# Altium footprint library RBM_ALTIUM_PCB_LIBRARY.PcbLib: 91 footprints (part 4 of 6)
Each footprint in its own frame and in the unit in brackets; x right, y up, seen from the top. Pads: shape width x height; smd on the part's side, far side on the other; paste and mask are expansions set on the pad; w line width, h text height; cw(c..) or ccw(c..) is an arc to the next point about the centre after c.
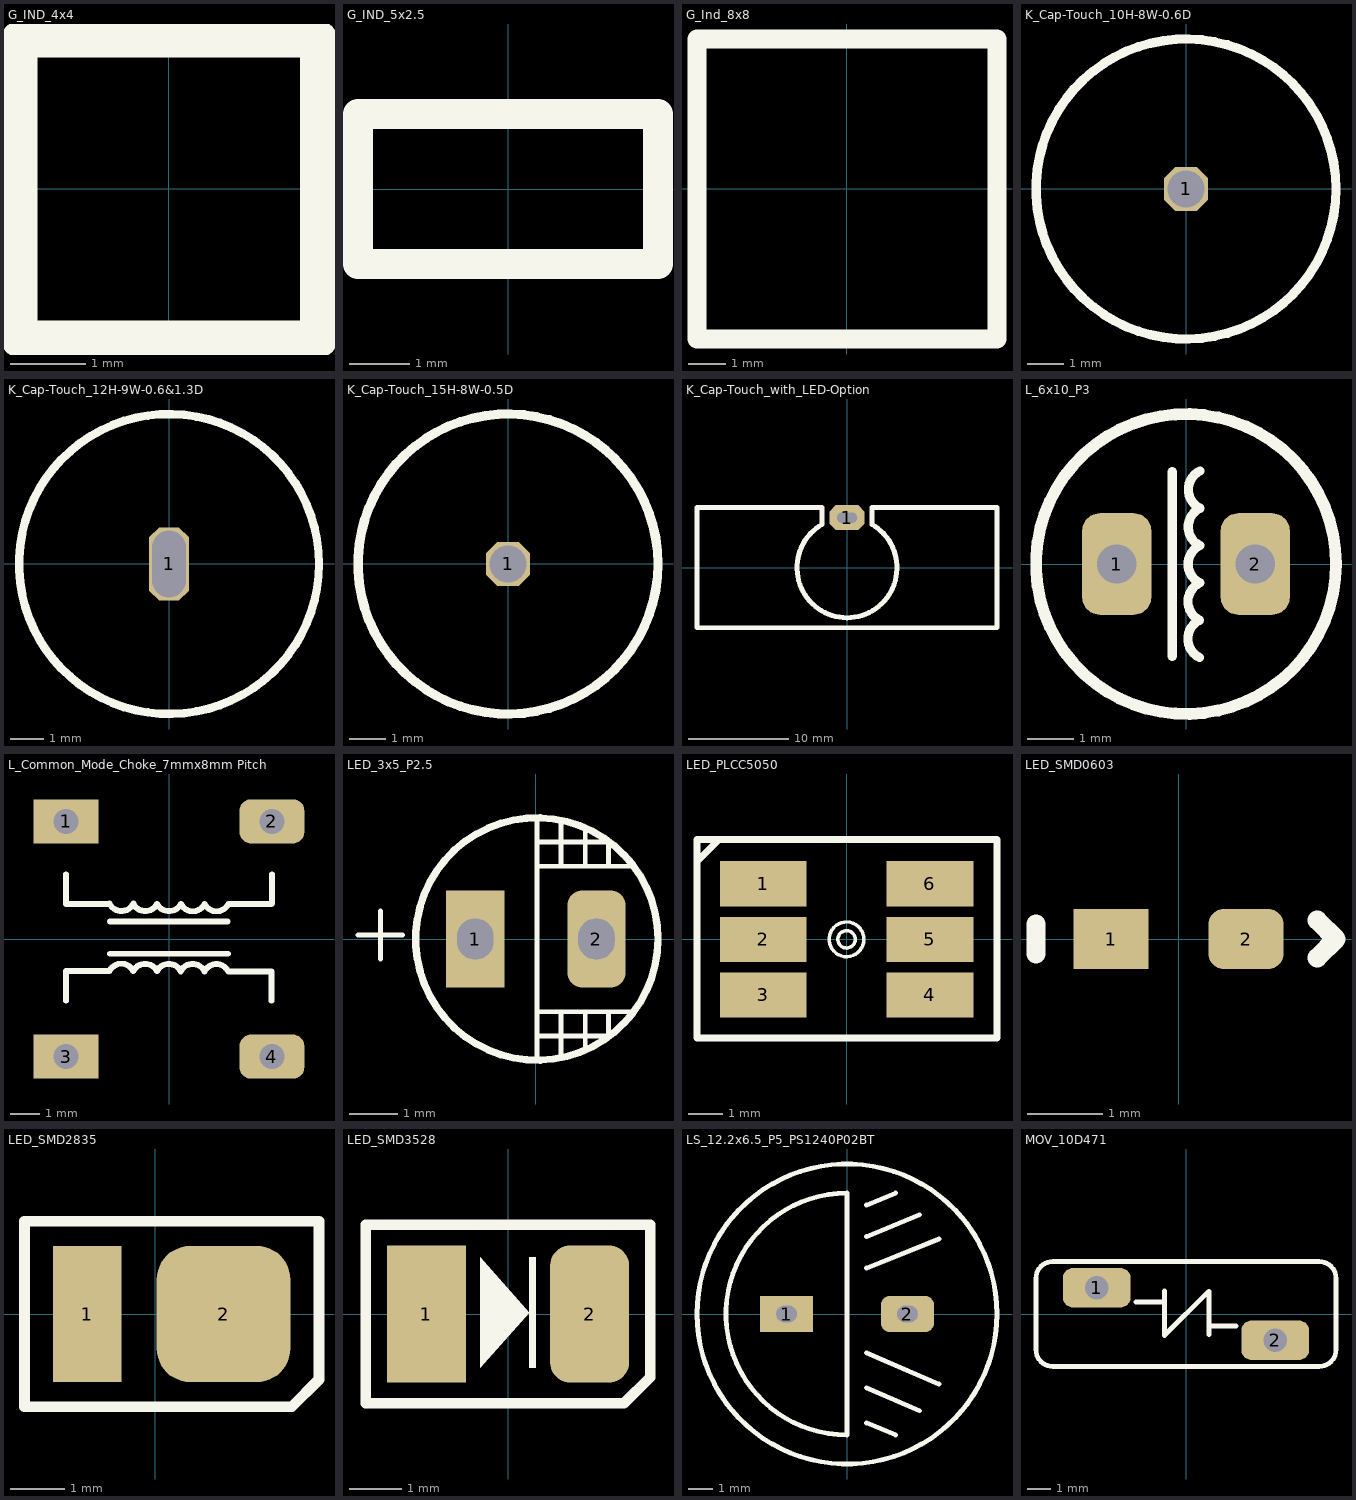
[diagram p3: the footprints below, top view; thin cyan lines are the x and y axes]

## G_IND_4x4 [mm]
Top Overlay:
  lines w0.5: -2,-2 -2,2 2,2 2,-2 -2,-2
3D body: height 8, standoff 0, extent -2.256,1.75 2.257,2.25
3D body: height 8, standoff 0, extent -2.25,-2.257 -1.75,2.256
3D body: height 8, standoff 0, extent -2.263,-2.25 2.25,-1.75
3D body: height 8, standoff 0, extent 1.75,-2.256 2.25,2.257

## G_IND_5x2.5 [mm]
Top Overlay:
  lines w0.5: -2.506,-1.244 -2.506,1.256 2.494,1.256 2.494,-1.244 -2.506,-1.244
3D body: height 8, standoff 0, extent 2.244,-1.48 2.744,1.492
3D body: height 8, standoff 0, extent -2.74,-1.494 2.727,-0.994
3D body: height 8, standoff 0, extent -2.756,-1.48 -2.256,1.492
3D body: height 8, standoff 0, extent -2.739,1.006 2.728,1.506

## G_Ind_8x8 [mm]
Top Overlay:
  lines w0.5: -3.994,-4.006 4.006,-4.006 4.006,3.994 -3.994,3.994 -3.994,-4.006
3D body: height 8, standoff 0, extent 3.756,-4.241 4.256,4.229
3D body: height 8, standoff 0, extent -4.229,-4.256 4.241,-3.756
3D body: height 8, standoff 0, extent -4.244,-4.241 -3.744,4.228
3D body: height 8, standoff 0, extent -4.228,3.744 4.241,4.244

## K_Cap-Touch_10H-8W-0.6D [mm]
pads (1):
  oct 1.2x1.2 / inner oct 1x1 / far side oct 2.5x2.5 hole 1: 1(0,0)
Top Overlay:
  circle w0.254: c0,0 r4.09
3D body: height 3, standoff -3, extent -0.258,-0.259 0.26,0.26
3D body: height 10, standoff 0, extent -4,-3.997 4,3.997

## K_Cap-Touch_12H-9W-0.6&1.3D [mm]
pads (1):
  oct 1.2x2.2 / inner oct 1x1 / far side oct 3x3 hole 2 slot 1 at 0 deg: 1(0,0)
Top Overlay:
  circle w0.254: c0,0 r4.5
3D body: height 12, standoff 0, extent -4.5,-4.5 4.5,4.5
3D body: height 5, standoff -3, extent -0.3,-0.7 0.3,0.7

## K_Cap-Touch_15H-8W-0.5D [mm]
pads (1):
  oct 1.2x1.2 / inner oct 1x1 / far side oct 2.5x2.5 hole 1: 1(0,0)
Top Overlay:
  circle w0.254: c0,0 r4.09
3D body: height 3, standoff -3, extent -0.258,-0.259 0.26,0.26
3D body: height 15, standoff 0, extent -4,-3.997 4,3.997

## K_Cap-Touch_with_LED-Option [mm]
pads (1):
  oct 3.5x2.5 hole 2 slot 1 at 90 deg: 1(0,5)
Top Overlay:
  lines w0.5: -15,-6 15,-6 15,6 2.5,6 2.5,4.33 cw(c0,0) -2.5,4.33 -2.5,6 -15,6 -15,-6
3D body "Touch_Spring.STEP": height 11.25, standoff -2.76, extent -5.25,-5.25 5.25,5.25

## L_6x10_P3 [mm]
pads (2):
  rrect50% 1.5x2.2 hole 0.85: 1(-1.5,0) 2(1.5,0)
Top Overlay:
  circle w0.254: c0,0 r3.25
  lines w0.2: -0.3,-2 -0.3,2 ; 0.293,-2.025 cw(c0.489,-1.622) 0.295,-1.217 cw(c0.492,-0.813) 0.298,-0.408 cw(c0.494,-0.005) 0.3,0.4 cw(c0.497,0.804) 0.302,1.208 cw(c0.499,1.612) 0.305,2.017
3D body: height 2, standoff -1, extent 1.202,-0.299 1.8,0.3
3D body: height 2, standoff -1, extent -1.799,-0.299 -1.201,0.299
3D body: height 13, standoff 10, extent -3.242,-3.316 3.258,3.177
3D body: height 3.25, standoff 0.25, extent -3.242,-3.316 3.258,3.177
3D body: height 11.5, standoff 0.5, extent -2.993,-3.07 3.006,2.93

## L_Common_Mode_Choke_7mmx8mm Pitch [mm] "1~22mH, 1000~200mA"
pads (4):
  rect 2.2x1.5 hole 0.85: 1(-3.5,4) 3(-3.5,-4)
  rrect50% 2.2x1.5 hole 0.85: 2(3.5,4) 4(3.5,-4)
Top Overlay:
  lines w0.2: -3.5,-2.1 -3.5,-1.093 -2.025,-1.093 cw(c-1.622,-1.289) -1.217,-1.095 cw(c-0.813,-1.292) -0.408,-1.098 cw(c-0.005,-1.294) 0.4,-1.1 cw(c0.804,-1.297) 1.208,-1.102 cw(c1.612,-1.299) 2.017,-1.105 3.488,-1.105 3.488,-2.1 ; -3.5,2.2 -3.5,1.193 -2.034,1.193 -2.022,1.205 ccw(c-1.617,1.399) -1.213,1.202 ccw(c-0.808,1.397) -0.405,1.2 ccw(c0,1.394) 0.404,1.198 ccw(c0.808,1.392) 1.212,1.195 ccw(c1.617,1.389) 2.02,1.193 3.488,1.193 3.5,1.205 3.5,2.2 ; -2.005,0.6 1.995,0.6 ; -2,-0.5 2,-0.5

## LED_3x5_P2.5 [mm]
pads (2):
  rect 1.2x2 hole 0.85 slot 0.75 at 0 deg: 1(-1.25,0)
  rrect50% 1.2x2 hole 0.85 slot 0.75 at 0 deg: 2(1.25,0)
Top Overlay:
  circle w0.15: c0.02,0 r2.5
  lines w0.1: -3.67,0.083 -2.754,0.083 ; -3.203,-0.417 -3.203,0.583 ; 0.02,-2.5 0.02,2.5 ; 0.02,-2 1.5,-2 1.5,-1.5 ; 0.02,-1.5 2.014,-1.5 ; 0.02,1.5 2.014,1.5 ; 0.02,2 1.5,2 1.5,1.5 ; 0.52,-2.4 0.52,-1.5 ; 0.52,1.5 0.52,2.4 ; 1.02,-2.3 1.02,-1.5 ; 1.02,1.5 1.02,2.3
3D body "LED_3x5_P2.5.STEP": height 7.38, standoff -1.17, extent -1.974,-1.498 2.014,1.994

## LED_PLCC5050 [mm] "EDISON RGB .2W"
pads (6):
  rect 2.5x1.3 smd: 1(-2.4,1.6) 2(-2.4,0) 3(-2.4,-1.6) 4(2.4,-1.6) 5(2.4,0) 6(2.4,1.6)
Top Overlay:
  circle w0.1: c0,0 r0.25
  circle w0.1: c0,0 r0.5
  lines w0.2: -4.305,2.235 -3.67,2.87 ; -4.305,-2.845 -4.305,2.87 4.331,2.87 4.331,-2.845 -4.305,-2.845
3D body "User Library-APA102C.step": height 1.51, standoff -0.04, extent -2.75,-2.5 2.75,2.5

## LED_SMD0603 [mm]
pads (2):
  rect 1x0.8 smd: 1(-0.9,0)
  rrect50% 1x0.8 smd: 2(0.9,0)
Top Overlay:
  lines w0.254: -1.9,-0.2 -1.9,0.2 ; 1.85,-0.25 2.1,0 1.85,0.25
3D body "ALSRobot-LED0603(R).step": height 0.6, standoff 0, extent -0.81,-0.4 0.81,0.4

## LED_SMD2835 [mm]
pads (2):
  rect 1.25x2.5 smd: 1(-1.25,0)
  rrect50% 2.45x2.5 smd: 2(1.25,0)
Top Overlay:
  lines w0.2: -2.4,-1.7 2.5,-1.7 3,-1.2 3,1.7 -2.4,1.7 -2.4,-1.7
3D body "LED_SMD-2835.STEP": height 0.7, standoff -0.02, extent -1.547,-1.4 2.017,1.4

## LED_SMD3528 [mm]
pads (2):
  rect 1.5x2.6 smd: 1(-1.55,0)
  rrect50% 1.5x2.6 smd: 2(1.55,0)
Top Overlay:
  region: 0.525,1.075 0.4,1.075 0.4,-1.025 0.525,-1.025
  region: -0.525,-1.025 -0.525,1.075 0.4,0.025
  region: 2.5,1.6
  lines w0.2: -2.7,-1.7 -2.7,1.7 2.7,1.7 2.7,-1.2 2.2,-1.7 -2.7,-1.7
3D body "LED_Osram_Led_PLCC4-2.step": height 1.95, standoff 0, extent -1.8,-1.4 1.7,1.4

## LS_12.2x6.5_P5_PS1240P02BT [mm] "PS1240P02BT, ø12.2x6.5 P5 70dB 4kHz 3~30V"
pads (2):
  rect 2.2x1.5 hole 0.7 slot 0.85 at 0 deg: 1(-2.5,0)
  rrect50% 2.2x1.5 hole 0.7 slot 0.85 at 0 deg: 2(2.5,0)
Top Overlay:
  circle w0.2: c0,0 r6.2
  lines w0.2: 0.8,-4.5 2,-5 ; 0.8,-3.046 3,-4 ; 0.8,-1.6 3.8,-2.9 ; 0.8,1.9 3.8,3.1 ; 0.8,3.2 3,4.1 ; 0.8,4.5 2,5 ; 0,-5 cw(c0,0) 0,5 0,-5
3D body: height 6.75, standoff 0.25, extent -6.1,-6.097 6.1,6.097
3D body: height 1, standoff -1, extent -2.829,-0.329 -2.171,0.329
3D body: height 1, standoff -1, extent 2.173,-0.329 2.83,0.33
3D body: height 6.8, standoff 0.3, extent -1.494,-1.497 1.494,1.497

## MOV_10D471 [mm]
pads (2):
  rrect50% 2.85x1.65 hole 1: 1(-3.75,1.1) 2(3.75,-1.1)
Top Overlay:
  lines w0.1: 0.998,-0.51 1.009,-0.5
  lines w0.2: -5.1,2.2 5.6,2.2 cw(c5.6,1.5) 6.3,1.5 6.3,-1.5 cw(c5.6,-1.5) 5.6,-2.2 -5.6,-2.2 cw(c-5.6,-1.5) -6.3,-1.5 -6.3,1.5 cw(c-5.6,1.5) -5.6,2.2 -4.9,2.2 ; -2.1,0.499 -0.921,0.499 ; -0.908,0.967 -0.908,-0.903 0.954,0.959 ; 0.967,-0.875 0.967,0.959 ; 1.009,-0.5 2.1,-0.5
3D body "User Library-S10K275.STEP": height 13.55, standoff -1.95, extent -6,-1.9 6,1.901
3D body: height 3, standoff -2, extent -4.158,0.691 -3.342,1.509
3D body: height 3, standoff -2, extent 3.343,-1.509 4.16,-0.691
